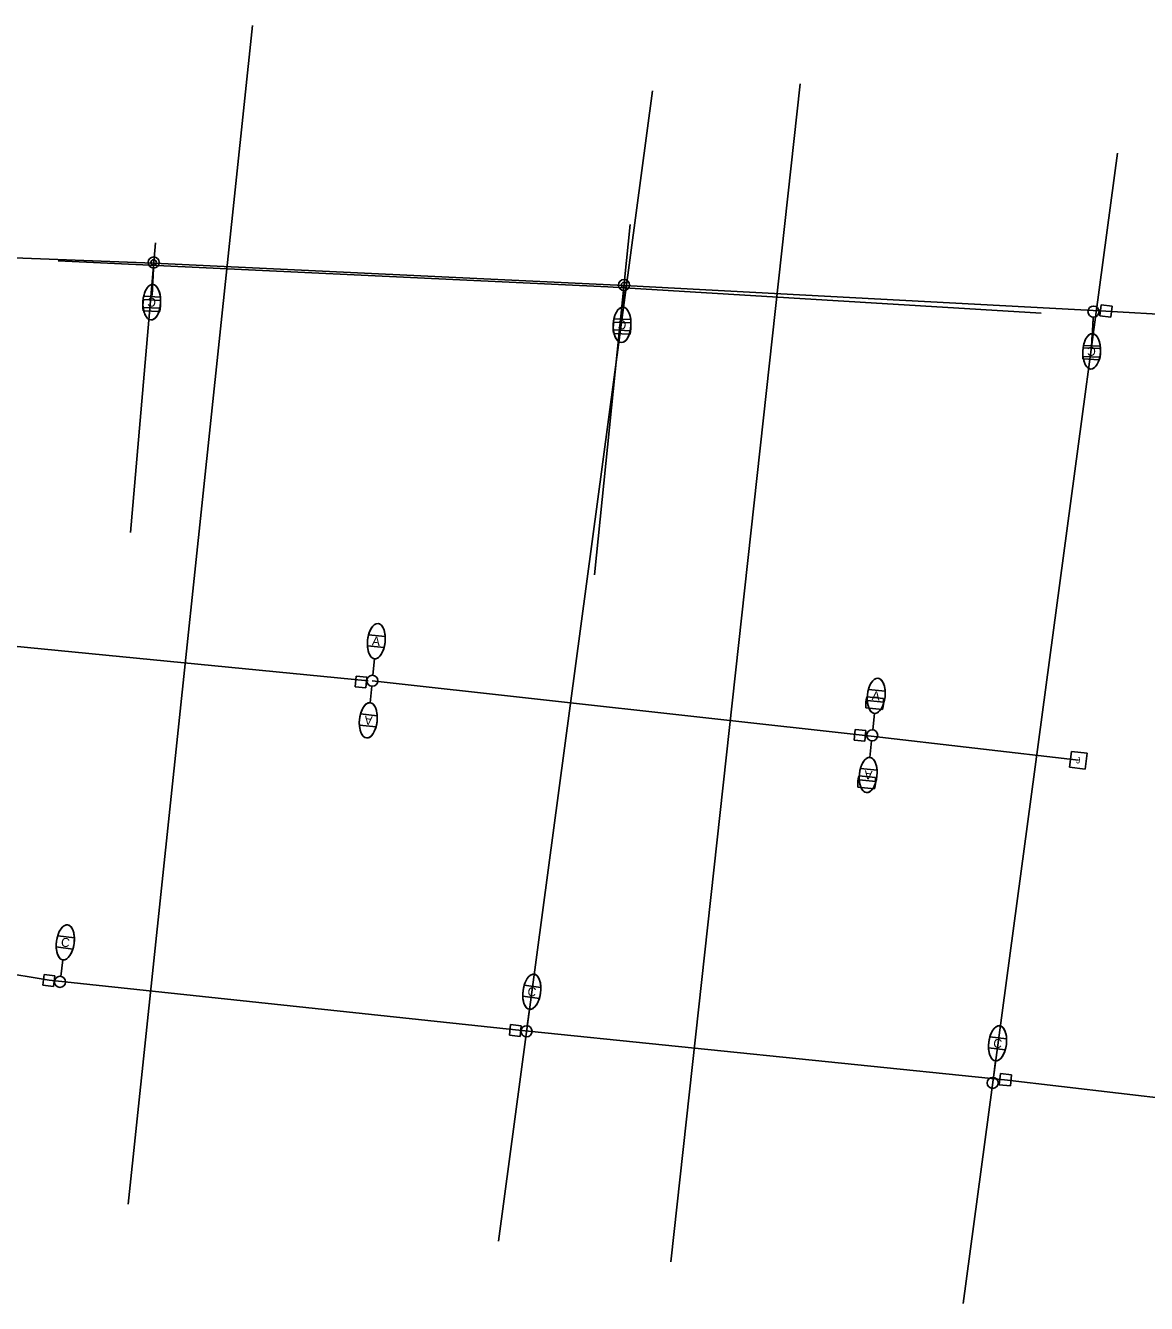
# Model space of a CAD drawing. Extents: x 915723 to 927758, y 636394 to 638609.
# Drawn here: x 926734 to 927236, y 636432 to 637004 of the extents above; entities that cross this region are included whole.
import ezdxf

# ---------------------------------------------------------------- set-up
doc = ezdxf.new("R2010")
doc.units = 0
for name, color, linetype in [('ConduitBM', 7, 'Continuous'), ('ConduitOT', 7, 'Continuous'), ('DrShaftConc', 7, 'Continuous'), ('Masonry_h', 7, 'Continuous'), ('Miscellaneous2', 7, 'Continuous'), ('PoleLight', 7, 'Continuous'), ('PullBox', 7, 'Continuous'), ('TextStructuresLabel', 7, 'Continuous')]:
    doc.layers.add(name, color=color, linetype=linetype)

msp = doc.modelspace()

# ---------------------------------------------------------------- linework, layer by layer
at = {"layer": 'ConduitBM'}
for p, q in [((926672.98, 636731.25), (926887.33, 636710.33)), ((926889.1, 636710.32), (927112.56, 636685.5)), ((927112.56, 636685.5), (927205.3, 636674.71))]:
    msp.add_line(p, q, dxfattribs=at)
at = {"layer": 'ConduitOT'}
for p, q in [((926791.2, 636897.34), (926641.08, 636902.83)), ((927001.86, 636887.23), (926791.37, 636897.34)), ((927217.6, 636875.85), (927002.03, 636887.22)), ((927427.58, 636863), (927217.6, 636875.85)), ((926640.67, 636593.55), (926744.36, 636576.23)), ((926744.36, 636576.23), (926953.25, 636553.97)), ((926953.25, 636553.97), (927172.16, 636531.7)), ((927381.44, 636507.28), (927172.16, 636531.7))]:
    msp.add_line(p, q, dxfattribs=at)
at = {"layer": 'DrShaftConc'}
for p, q in [((926835.52, 637003.66), (926779.85, 636476.02)), ((927080.67, 636977.52), (927022.77, 636450.12)), ((927004.6, 636914.66), (926988.7, 636757.71)), ((926791.99, 636906.45), (926780.79, 636776.75)), ((926994.53, 636886.68), (926748.42, 636898.38)), ((926994.55, 636886.68), (927188.66, 636874.95))]:
    msp.add_line(p, q, dxfattribs=at)
for centre in [(926791.22, 636897.6), (927001.85, 636887.49)]:
    msp.add_circle(centre, 1.25, dxfattribs=at)
at = {"layer": 'Masonry_h'}
for p, q in [((927014.66, 636974.49), (926945.57, 636459.46)), ((927222.8, 636946.57), (927153.71, 636431.54)), ((926791.11, 636894.85), (926790.54, 636882.86)), ((926791.11, 636894.85), (926790.54, 636882.86)), ((927211.92, 636872.04), (927211.19, 636860.06)), ((927211.92, 636872.04), (927211.19, 636860.06)), ((927211.92, 636872.04), (927211.19, 636860.06)), ((927211.92, 636872.04), (927211.19, 636860.06)), ((927211.74, 636869.05), (927211.37, 636863.06))]:
    msp.add_line(p, q, dxfattribs=at)
at = {"layer": 'Miscellaneous2'}
for p, q in [((926794.2, 636880.62), (926786.69, 636880.97)), ((926786.69, 636880.97), (926786.69, 636880.97)), ((926794.25, 636882.12), (926786.74, 636882.47)), ((926786.74, 636882.47), (926786.74, 636882.47)), ((926786.46, 636875.98), (926786.46, 636875.98)), ((926786.46, 636875.98), (926793.96, 636875.62)), ((926786.51, 636877.48), (926786.51, 636877.48)), ((926786.51, 636877.48), (926794.01, 636877.12)), ((927004.83, 636870.51), (926997.32, 636870.86)), ((926997.32, 636870.86), (926997.32, 636870.86)), ((927004.88, 636872), (926997.37, 636872.36)), ((926997.37, 636872.36), (926997.37, 636872.36)), ((926997.08, 636865.87), (926997.08, 636865.87)), ((926997.08, 636865.87), (927004.59, 636865.51)), ((926997.13, 636867.37), (926997.13, 636867.37)), ((926997.13, 636867.37), (927004.64, 636867.01)), ((927215.08, 636859.06), (927207.58, 636859.41)), ((927207.58, 636859.41), (927207.58, 636859.41)), ((927215.13, 636860.13), (927207.62, 636860.48)), ((927207.62, 636860.48), (927207.62, 636860.48)), ((927207.34, 636854.42), (927207.34, 636854.42)), ((927207.34, 636854.42), (927214.85, 636854.06)), ((927207.38, 636855.49), (927207.38, 636855.49)), ((927207.38, 636855.49), (927214.89, 636855.13)), ((926894.91, 636730.15), (926887.44, 636730.91)), ((926887.44, 636730.91), (926887.44, 636730.91)), ((926886.93, 636725.93), (926886.93, 636725.93)), ((926886.93, 636725.93), (926894.41, 636725.18)), ((927118.09, 636702.41), (927110.61, 636703.17)), ((927110.61, 636703.17), (927110.61, 636703.17)), ((927118.77, 636705.7), (927111.29, 636706.46)), ((927111.29, 636706.46), (927111.29, 636706.46)), ((927110.11, 636698.2), (927110.11, 636698.2)), ((927110.11, 636698.2), (927117.58, 636697.44)), ((927110.79, 636701.48), (927110.79, 636701.48)), ((927110.79, 636701.48), (927118.26, 636700.72)), ((926883.34, 636690.48), (926883.34, 636690.48)), ((926883.34, 636690.48), (926890.81, 636689.72)), ((926891.32, 636694.69), (926883.84, 636695.45)), ((926883.84, 636695.45), (926883.84, 636695.45)), ((927114.49, 636666.95), (927107.02, 636667.71)), ((927107.02, 636667.71), (927107.02, 636667.71)), ((927115.17, 636670.24), (927107.69, 636671)), ((927107.69, 636671), (927107.69, 636671)), ((927106.51, 636662.74), (927106.51, 636662.74)), ((927106.51, 636662.74), (927113.99, 636661.98)), ((927107.19, 636666.02), (927107.19, 636666.02)), ((927107.19, 636666.02), (927114.67, 636665.27)), ((926755.69, 636595.16), (926748.24, 636596.16)), ((926755.69, 636595.16), (926755.69, 636595.16)), ((926747.57, 636591.2), (926755.02, 636590.21)), ((926755.02, 636590.21), (926755.02, 636590.21)), ((926964.6, 636573.05), (926957.15, 636574.05)), ((926964.6, 636573.05), (926964.6, 636573.05)), ((926956.49, 636569.1), (926963.94, 636568.1)), ((926963.94, 636568.1), (926963.94, 636568.1)), ((927173.17, 636550), (927165.71, 636550.92)), ((927173.17, 636550), (927173.17, 636550)), ((927165.1, 636545.95), (927172.56, 636545.04)), ((927172.56, 636545.04), (927172.56, 636545.04))]:
    msp.add_line(p, q, dxfattribs=at)
for centre, major_axis, start_param, end_param in [((926790.33, 636878.3), (0.38, 7.91), 1.249648, 1.891946), ((926790.38, 636879.8), (0.38, 7.91), 1.249648, 1.891946), ((926790.33, 636878.3), (0.38, 7.91), 4.391271, 5.033538), ((926790.38, 636879.8), (0.38, 7.91), 4.391271, 5.033538), ((926790.33, 636878.3), (0.38, 7.91), 4.391241, 4.391271), ((926790.38, 636879.8), (0.38, 7.91), 4.391241, 4.391271), ((927000.95, 636868.19), (0.38, 7.91), 1.249648, 1.891946), ((927001, 636869.69), (0.38, 7.91), 1.249648, 1.891946), ((927000.95, 636868.19), (0.38, 7.91), 4.391271, 5.033538), ((927001, 636869.69), (0.38, 7.91), 4.391271, 5.033538), ((927000.95, 636868.19), (0.38, 7.91), 4.391241, 4.391271), ((927001, 636869.69), (0.38, 7.91), 4.391241, 4.391271), ((927211.21, 636856.74), (0.38, 7.91), 1.249648, 1.891946), ((927211.25, 636857.81), (0.38, 7.91), 1.249648, 1.891946), ((927211.21, 636856.74), (0.38, 7.91), 4.391271, 5.033538), ((927211.25, 636857.81), (0.38, 7.91), 4.391271, 5.033538), ((927211.21, 636856.74), (0.38, 7.91), 4.391241, 4.391271), ((927211.25, 636857.81), (0.38, 7.91), 4.391241, 4.391271), ((926890.92, 636728.04), (0.8, 7.88), 1.249648, 1.891946), ((926890.92, 636728.04), (0.8, 7.88), 4.391271, 5.033538), ((926890.92, 636728.04), (0.8, 7.88), 4.391241, 4.391271), ((927114.1, 636700.3), (0.8, 7.88), 1.249648, 1.891946), ((927114.78, 636703.59), (0.8, 7.88), 1.249648, 1.891946), ((927114.1, 636700.3), (0.8, 7.88), 4.391271, 5.033538), ((927114.78, 636703.59), (0.8, 7.88), 4.391271, 5.033538), ((927114.1, 636700.3), (0.8, 7.88), 4.391241, 4.391271), ((927114.78, 636703.59), (0.8, 7.88), 4.391241, 4.391271), ((926887.33, 636692.58), (0.8, 7.88), 1.249648, 1.891946), ((926887.33, 636692.58), (0.8, 7.88), 4.391271, 5.033538), ((926887.33, 636692.58), (0.8, 7.88), 4.391241, 4.391271), ((927110.5, 636664.85), (0.8, 7.88), 1.249648, 1.891946), ((927111.18, 636668.13), (0.8, 7.88), 1.249648, 1.891946), ((927111.18, 636668.13), (0.8, 7.88), 4.391271, 5.033538), ((927110.5, 636664.85), (0.8, 7.88), 4.391271, 5.033538), ((927110.5, 636664.85), (0.8, 7.88), 4.391241, 4.391271), ((927111.18, 636668.13), (0.8, 7.88), 4.391241, 4.391271), ((926751.63, 636593.18), (-1.05, -7.85), 4.391271, 5.033538), ((926751.63, 636593.18), (-1.05, -7.85), 4.391241, 4.391271), ((926751.63, 636593.18), (-1.05, -7.85), 1.249648, 1.891946), ((926960.55, 636571.08), (-1.05, -7.85), 4.391271, 5.033538), ((926960.55, 636571.08), (-1.05, -7.85), 4.391241, 4.391271), ((926960.55, 636571.08), (-1.05, -7.85), 1.249648, 1.891946), ((927169.13, 636547.98), (-0.97, -7.86), 4.391271, 5.033538), ((927169.13, 636547.98), (-0.97, -7.86), 4.391241, 4.391271), ((927169.13, 636547.98), (-0.97, -7.86), 1.249648, 1.891946)]:
    msp.add_ellipse(centre, major_axis=major_axis, ratio=0.5, start_param=start_param, end_param=end_param, dxfattribs=at)
at = {"layer": 'PoleLight'}
for p, q in [((926791.11, 636895.12), (926790.75, 636887.71)), ((927001.73, 636885.01), (927001.38, 636877.6)), ((926786.74, 636882.47), (926794.25, 636882.12)), ((926794.01, 636877.12), (926786.51, 636877.48)), ((926997.37, 636872.36), (927004.88, 636872)), ((927211.98, 636873.14), (927211.63, 636865.72)), ((927004.64, 636867.01), (926997.13, 636867.37)), ((927207.62, 636860.48), (927215.13, 636860.13)), ((927214.89, 636855.13), (927207.38, 636855.49)), ((926887.44, 636730.91), (926894.91, 636730.15)), ((926894.41, 636725.18), (926886.93, 636725.93)), ((926889.37, 636712.77), (926890.12, 636720.16)), ((926888.88, 636707.85), (926888.13, 636700.46)), ((927111.29, 636706.46), (927118.77, 636705.7)), ((927118.26, 636700.72), (927110.79, 636701.48)), ((926890.81, 636689.72), (926883.34, 636690.48)), ((926883.84, 636695.45), (926891.32, 636694.69)), ((927113.23, 636688.32), (927113.98, 636695.71)), ((927112.73, 636683.4), (927111.98, 636676.01)), ((927107.69, 636671), (927115.17, 636670.24)), ((927114.67, 636665.27), (927107.19, 636666.02)), ((926748.24, 636596.16), (926755.69, 636595.16)), ((926755.02, 636590.21), (926747.57, 636591.2)), ((926749.59, 636577.97), (926750.58, 636585.33)), ((926957.15, 636574.05), (926964.6, 636573.05)), ((926963.94, 636568.1), (926956.49, 636569.1)), ((926958.51, 636555.87), (926959.49, 636563.23)), ((927165.71, 636550.92), (927173.17, 636550)), ((927172.56, 636545.04), (927165.1, 636545.95)), ((927167.26, 636532.75), (927168.16, 636540.11))]:
    msp.add_line(p, q, dxfattribs=at)
for centre in [(926791.22, 636897.6), (926791.22, 636897.6), (927001.85, 636887.49), (927001.85, 636887.49), (927212.1, 636875.61), (927212.1, 636875.61), (926889.13, 636710.31), (926889.13, 636710.31), (927112.98, 636685.86), (927112.98, 636685.86), (926749.26, 636575.52), (926749.26, 636575.52), (926958.18, 636553.41), (926958.18, 636553.41), (927166.95, 636530.29), (927166.95, 636530.29)]:
    msp.add_circle(centre, 2.48, dxfattribs=at)
for centre, major_axis in [((926790.38, 636879.8), (0.38, 7.91)), ((927001, 636869.69), (0.38, 7.91)), ((927211.25, 636857.81), (0.38, 7.91)), ((926890.92, 636728.04), (0.8, 7.88)), ((927114.78, 636703.59), (0.8, 7.88)), ((926887.33, 636692.58), (0.8, 7.88)), ((927111.18, 636668.13), (0.8, 7.88)), ((926751.63, 636593.18), (-1.05, -7.85)), ((926960.55, 636571.08), (-1.05, -7.85)), ((927169.13, 636547.98), (-0.97, -7.86))]:
    msp.add_ellipse(centre, major_axis=major_axis, ratio=0.5, dxfattribs=at)
for centre, major_axis, start_param, end_param in [((926790.38, 636879.8), (0.38, 7.91), 0.847605, 1.249648), ((926790.38, 636879.8), (0.38, 7.91), 0, 0.847605), ((926790.38, 636879.8), (0.38, 7.91), 5.033538, 6.283185), ((926790.38, 636879.8), (0.38, 7.91), 1.891945, 4.391241), ((927001, 636869.69), (0.38, 7.91), 0.847605, 1.249648), ((927001, 636869.69), (0.38, 7.91), 0, 0.847605), ((927001, 636869.69), (0.38, 7.91), 5.033538, 6.283185), ((927001, 636869.69), (0.38, 7.91), 1.891945, 4.391241), ((927211.25, 636857.81), (0.38, 7.91), 0.847605, 1.249648), ((927211.25, 636857.81), (0.38, 7.91), 0, 0.847605), ((927211.25, 636857.81), (0.38, 7.91), 5.033538, 6.283185), ((927211.25, 636857.81), (0.38, 7.91), 1.891945, 4.391241), ((926890.92, 636728.04), (0.8, 7.88), 0.847605, 1.249648), ((926890.92, 636728.04), (0.8, 7.88), 0, 0.847605), ((926890.92, 636728.04), (0.8, 7.88), 5.033538, 6.283185), ((926890.92, 636728.04), (0.8, 7.88), 1.891945, 4.391241), ((927114.78, 636703.59), (0.8, 7.88), 0.847605, 1.249648), ((927114.78, 636703.59), (0.8, 7.88), 0, 0.847605), ((927114.78, 636703.59), (0.8, 7.88), 5.033538, 6.283185), ((926887.33, 636692.58), (0.8, 7.88), 0.847605, 1.249648), ((926887.33, 636692.58), (0.8, 7.88), 0, 0.847605), ((926887.33, 636692.58), (0.8, 7.88), 5.033538, 6.283185), ((927114.78, 636703.59), (0.8, 7.88), 1.891945, 4.391241), ((926887.33, 636692.58), (0.8, 7.88), 1.891945, 4.391241), ((927111.18, 636668.13), (0.8, 7.88), 0.847605, 1.249648), ((927111.18, 636668.13), (0.8, 7.88), 0, 0.847605), ((927111.18, 636668.13), (0.8, 7.88), 5.033538, 6.283185), ((927111.18, 636668.13), (0.8, 7.88), 1.891945, 4.391241), ((926751.63, 636593.18), (-1.05, -7.85), 1.891945, 4.391241), ((926751.63, 636593.18), (-1.05, -7.85), 5.033538, 6.283185), ((926751.63, 636593.18), (-1.05, -7.85), 0, 0.847605), ((926751.63, 636593.18), (-1.05, -7.85), 0.847605, 1.249648), ((926960.55, 636571.08), (-1.05, -7.85), 1.891945, 4.391241), ((926960.55, 636571.08), (-1.05, -7.85), 5.033538, 6.283185), ((926960.55, 636571.08), (-1.05, -7.85), 0, 0.847605), ((926960.55, 636571.08), (-1.05, -7.85), 0.847605, 1.249648), ((927169.13, 636547.98), (-0.97, -7.86), 1.891945, 4.391241), ((927169.13, 636547.98), (-0.97, -7.86), 5.033538, 6.283185), ((927169.13, 636547.98), (-0.97, -7.86), 0, 0.847605), ((927169.13, 636547.98), (-0.97, -7.86), 0.847605, 1.249648)]:
    msp.add_ellipse(centre, major_axis=major_axis, ratio=0.5, start_param=start_param, end_param=end_param, dxfattribs=at)
at = {"layer": 'PullBox'}
for p, q in [((927214.88, 636873.69), (927215.46, 636878.66)), ((927219.85, 636873.12), (927214.88, 636873.69)), ((927215.46, 636878.66), (927220.42, 636878.09)), ((927220.42, 636878.09), (927219.85, 636873.12)), ((926881.42, 636707.56), (926881.83, 636712.35)), ((926886.2, 636707.16), (926881.42, 636707.56)), ((926881.83, 636712.35), (926886.61, 636711.94)), ((926886.61, 636711.94), (926886.2, 636707.16)), ((927104.9, 636683.68), (927105.31, 636688.47)), ((927105.31, 636688.47), (927110.09, 636688.06)), ((927110.09, 636688.06), (927109.68, 636683.27)), ((927109.68, 636683.27), (927104.9, 636683.68)), ((927201.35, 636671.58), (927202.17, 636678.66)), ((927202.17, 636678.66), (927209.25, 636677.84)), ((927209.25, 636677.84), (927208.43, 636670.76)), ((927208.43, 636670.76), (927201.35, 636671.58)), ((926741.62, 636574.05), (926742.17, 636578.82)), ((926742.17, 636578.82), (926746.94, 636578.28)), ((926746.94, 636578.28), (926746.39, 636573.5)), ((926746.39, 636573.5), (926741.62, 636574.05)), ((926950.5, 636551.67), (926951.05, 636556.45)), ((926951.05, 636556.45), (926955.82, 636555.9)), ((926955.82, 636555.9), (926955.28, 636551.12)), ((926955.28, 636551.12), (926950.5, 636551.67)), ((927169.9, 636529.49), (927170.47, 636534.46)), ((927170.47, 636534.46), (927175.44, 636533.89)), ((927175.44, 636533.89), (927174.87, 636528.92)), ((927174.87, 636528.92), (927169.9, 636529.49))]:
    msp.add_line(p, q, dxfattribs=at)

# ---------------------------------------------------------------- texts
at = {"layer": 'ConduitOT'}
msp.add_text('J', height=2.85, rotation=353.4101, dxfattribs=at).set_placement((927204.18, 636673.41))
at = {"layer": 'TextStructuresLabel'}
for s, rotation, p in [('C', 177.277, (926792.34, 636881.71)), ('C', 177.277, (927002.97, 636871.59)), ('C', 177.277, (927213.22, 636859.72)), ('A', 354.2099, (926888.87, 636726.24)), ('A', 354.2099, (927112.72, 636701.79)), ('A', 174.2099, (926889.38, 636694.39)), ('A', 174.2099, (927113.24, 636669.93)), ('C', 352.3598, (926749.51, 636591.45)), ('C', 352.3598, (926958.42, 636569.34)), ('C', 352.985, (927167.03, 636546.22))]:
    msp.add_text(s, height=4, rotation=rotation, dxfattribs=at).set_placement(p)

doc.saveas('drawing.dxf')
